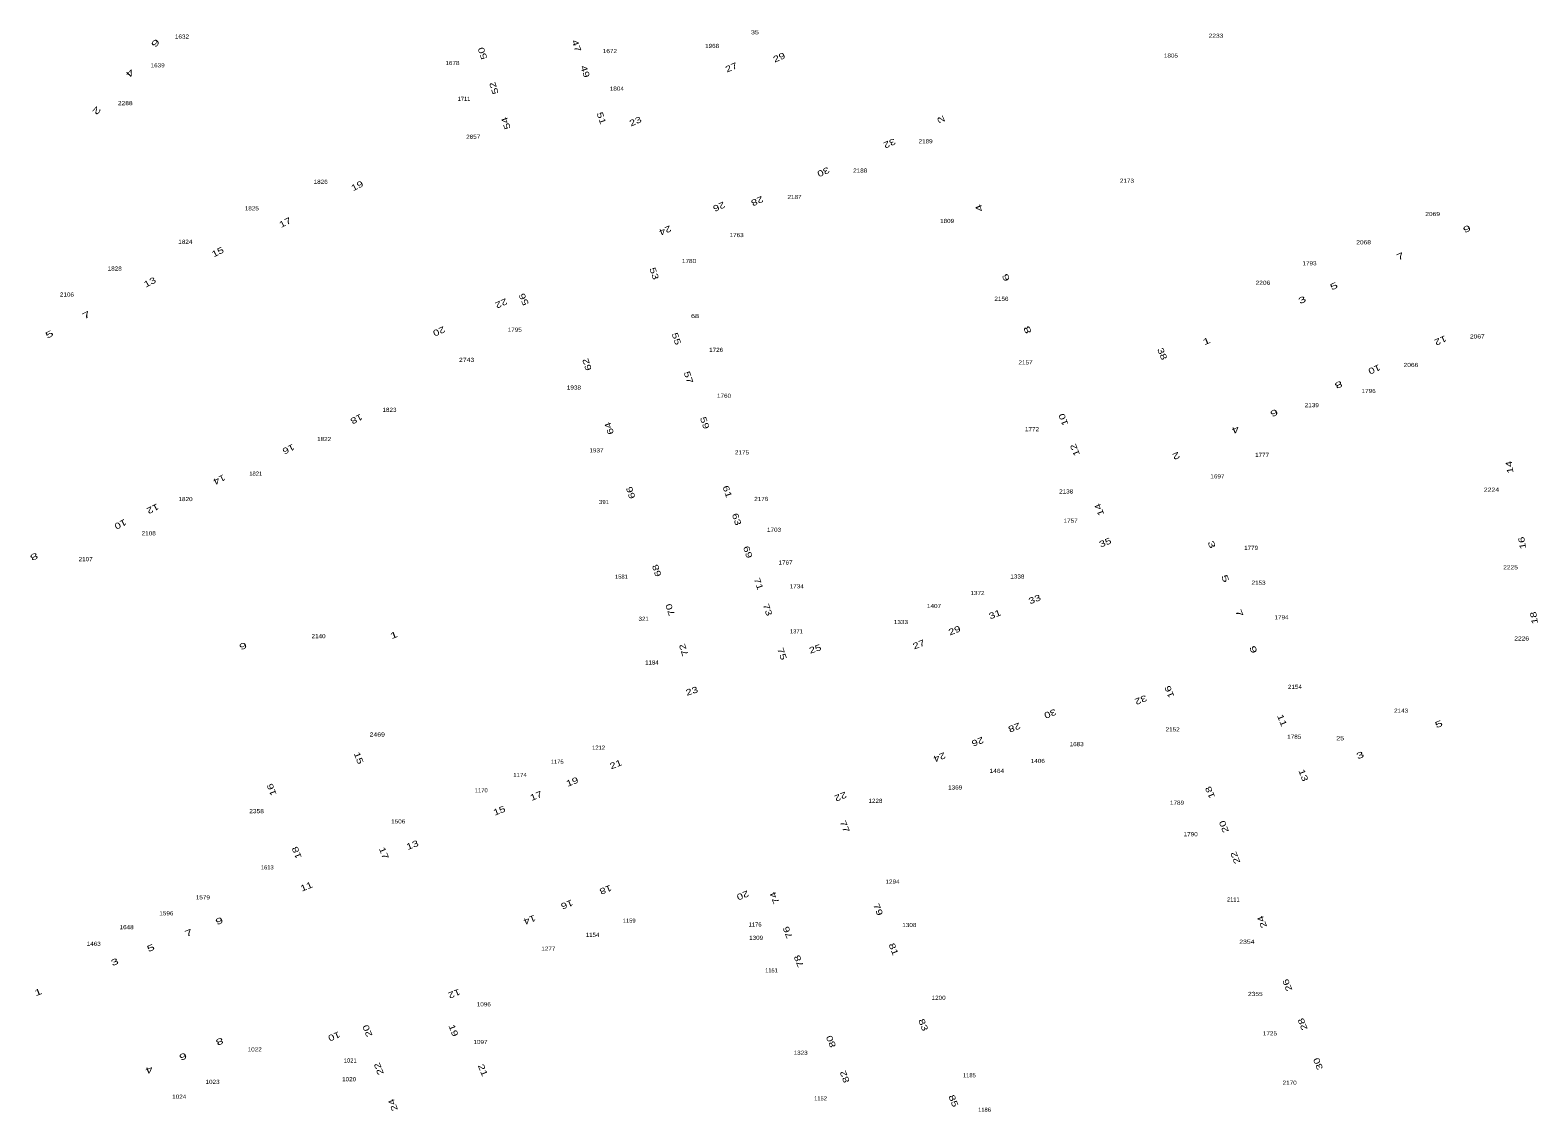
# Model space of a CAD drawing. Extents: x -828673 to -815583, y -1077737 to -1063807.
# Drawn here: x -821440 to -821074.1, y -1071841 to -1071578.4 of the extents above; entities that cross this region are included whole.
import ezdxf
from ezdxf.enums import TextEntityAlignment as Align

# ---------------------------------------------------------------- set-up
doc = ezdxf.new("R2010")
doc.units = 0
doc.header["$LTSCALE"] = 0.4
doc.layers.add('1', color=7, linetype='Continuous')
doc.layers.add('2', color=7, linetype='Continuous')

msp = doc.modelspace()

# ---------------------------------------------------------------- texts
at = {"layer": '1'}
for s, width, p in [('1632', 1.15, (-821403.179, -1071580.475)), ('35', 1.3, (-821264.142, -1071579.434)), ('2233', 1.2, (-821152.246, -1071580.27)), ('1672', 1.15, (-821299.33, -1071583.998)), ('1968', 1.15, (-821274.522, -1071582.747)), ('1639', 1.15, (-821409.077, -1071587.454)), ('1678', 1.15, (-821337.54, -1071586.895)), ('1805', 1.15, (-821163.179, -1071585.1)), ('1804', 1.15, (-821297.65, -1071593.105)), ('2288', 1.2, (-821416.942, -1071596.633)), ('2857', 1.15, (-821332.51, -1071604.802)), ('2189', 1.15, (-821222.729, -1071605.887)), ('2188', 1.15, (-821238.591, -1071613.005)), ('1826', 1.15, (-821369.518, -1071615.734)), ('2173', 1.15, (-821173.859, -1071615.469)), ('2187', 1.15, (-821254.536, -1071619.411)), ('1825', 1.15, (-821386.233, -1071622.171)), ('2069', 1.2, (-821099.682, -1071623.547)), ('1809', 1.15, (-821217.498, -1071625.231)), ('1824', 1.15, (-821402.364, -1071630.3)), ('1763', 1.15, (-821268.577, -1071628.664)), ('2068', 1.2, (-821116.425, -1071630.407)), ('1780', 1.15, (-821280.124, -1071634.961)), ('1828', 1.15, (-821419.504, -1071636.788)), ('1793', 1.15, (-821129.555, -1071635.512)), ('2206', 1.2, (-821140.877, -1071640.245)), ('2106', 1.15, (-821431.11, -1071643.099)), ('2156', 1.15, (-821204.317, -1071644.134)), ('68', 1.3, (-821278.674, -1071648.318)), ('1795', 1.15, (-821322.429, -1071651.647)), ('2067', 1.2, (-821088.837, -1071653.274)), ('1726', 1.15, (-821273.556, -1071656.53)), ('2743', 1.25, (-821334.095, -1071658.955)), ('2157', 1.15, (-821198.479, -1071659.573)), ('2066', 1.2, (-821104.944, -1071660.188)), ('1938', 1.15, (-821308.064, -1071665.676)), ('1760', 1.15, (-821271.63, -1071667.667)), ('1796', 1.15, (-821115.203, -1071666.516)), ('1823', 1.15, (-821352.833, -1071671.084)), ('2139', 1.15, (-821129.002, -1071669.948)), ('1822', 1.15, (-821368.693, -1071678.184)), ('1772', 1.15, (-821196.894, -1071675.784)), ('1937', 1.15, (-821302.597, -1071680.92)), ('2175', 1.15, (-821267.281, -1071681.424)), ('1777', 1.15, (-821141.068, -1071682.02)), ('1821', 1.05, (-821385.281, -1071686.567)), ('1697', 1.15, (-821151.912, -1071687.232)), ('1820', 1.15, (-821402.312, -1071692.75)), ('391', 1.1, (-821300.758, -1071693.452)), ('2176', 1.15, (-821262.596, -1071692.71)), ('2138', 1.15, (-821188.608, -1071690.899)), ('2224', 1.25, (-821085.404, -1071690.477)), ('2108', 1.15, (-821411.247, -1071701.048)), ('1703', 1.15, (-821259.499, -1071700.205)), ('1757', 1.15, (-821187.521, -1071697.986)), ('1779', 1.15, (-821143.731, -1071704.588)), ('2107', 1.15, (-821426.552, -1071707.335)), ('1767', 1.15, (-821256.71, -1071708.148)), ('1581', 1.05, (-821296.534, -1071711.586)), ('1338', 1.15, (-821200.453, -1071711.552)), ('2225', 1.2, (-821080.765, -1071709.322)), ('1734', 1.15, (-821253.99, -1071713.926)), ('1372', 1.15, (-821210.131, -1071715.559)), ('2153', 1.15, (-821141.924, -1071713.044)), ('1407', 1.15, (-821220.677, -1071718.699)), ('321', 1.1, (-821291.147, -1071721.809)), ('1333', 1.15, (-821228.712, -1071722.593)), ('1794', 1.15, (-821136.343, -1071721.447)), ('2140', 1.15, (-821370.03, -1071726.031)), ('1371', 1.05, (-821254.074, -1071724.854)), ('2226', 1.2, (-821078.074, -1071726.589)), ('1184', 1.1, (-821289.138, -1071732.416)), ('2154', 1.15, (-821133.1, -1071738.318)), ('2143', 1.15, (-821107.32, -1071744.115)), ('2152', 1.15, (-821162.771, -1071748.661)), ('2469', 1.25, (-821355.793, -1071749.908)), ('1683', 1.15, (-821186.061, -1071752.238)), ('1785', 1.15, (-821133.26, -1071750.444)), ('25', 1.3, (-821122.104, -1071750.816)), ('1212', 1.05, (-821302.074, -1071753.08)), ('1174', 1.1, (-821321.141, -1071759.71)), ('1175', 1.05, (-821312.121, -1071756.502)), ('1464', 1.2, (-821205.434, -1071758.728)), ('1406', 1.15, (-821195.501, -1071756.311)), ('1170', 1.05, (-821330.547, -1071763.431)), ('1369', 1.15, (-821215.544, -1071762.757)), ('1228', 1.15, (-821234.901, -1071766.003)), ('1789', 1.15, (-821161.704, -1071766.451)), ('2358', 1.2, (-821385.088, -1071768.513)), ('1506', 1.15, (-821350.705, -1071770.995)), ('1790', 1.15, (-821158.393, -1071774.105)), ('1613', 1.05, (-821382.494, -1071782.15)), ('1294', 1.15, (-821230.74, -1071785.609)), ('1579', 1.15, (-821398.111, -1071789.429)), ('1596', 1.15, (-821406.964, -1071793.304)), ('1159', 1.05, (-821294.657, -1071795.084)), ('1176', 1.05, (-821264.097, -1071796.027)), ('1308', 1.15, (-821226.674, -1071796.136)), ('1648', 1.15, (-821416.615, -1071796.665)), ('1154', 1.1, (-821303.542, -1071798.545)), ('1309', 1.15, (-821263.846, -1071799.25)), ('1463', 1.15, (-821424.603, -1071800.704)), ('1277', 1.15, (-821314.264, -1071801.879)), ('2354', 1.25, (-821144.749, -1071800.206)), ('1200', 1.15, (-821219.56, -1071813.817)), ('2355', 1.2, (-821142.691, -1071812.873)), ('1096', 1.15, (-821329.937, -1071815.398)), ('1097', 1.15, (-821330.749, -1071824.544)), ('1725', 1.15, (-821139.157, -1071822.452)), ('1022', 1.15, (-821385.527, -1071826.347)), ('1021', 1.05, (-821362.346, -1071829.039)), ('1323', 1.15, (-821253.038, -1071827.159)), ('1185', 1.05, (-821212.097, -1071832.621)), ('1023', 1.15, (-821395.752, -1071834.216)), ('1020', 1.15, (-821362.609, -1071833.575)), ('2170', 1.15, (-821134.37, -1071834.427)), ('1024', 1.15, (-821403.843, -1071837.807)), ('1152', 1.05, (-821248.218, -1071838.234)), ('1186', 1.05, (-821208.428, -1071840.991))]:
    msp.add_text(s, height=1, dxfattribs=dict(at, width=width)).set_placement(p, align=Align.CENTER)
for s, p in [('1711', (-821334.731, -1071595.606)), ('2111', (-821148.058, -1071789.951)), ('1151', (-821260.129, -1071807.157))]:
    msp.add_text(s, height=1, dxfattribs=at).set_placement(p, align=Align.CENTER)
at = {"layer": '2'}
for s, rotation, width, p in [('6', 229.001, 1.75, (-821410.1899, -1071581.075)), ('50', 108.716, 1.35, (-821329.5311, -1071583.8222)), ('47', 289.39, 1.35, (-821308.1439, -1071582.462)), ('27', 23.864, 1.35, (-821269.5729, -1071588.1427)), ('29', 23.793, 1.35, (-821257.9696, -1071585.7206)), ('4', 228.912, 1.75, (-821416.3701, -1071588.3801)), ('49', 288.306, 1.35, (-821306.0404, -1071588.6764)), ('52', 108.435, 1.35, (-821326.7669, -1071592.2522)), ('2', 228.988, 1.75, (-821424.4225, -1071597.4683)), ('54', 108.779, 1.35, (-821323.8645, -1071600.7869)), ('51', 288.402, 1.35, (-821302.093, -1071600.0187)), ('23', 23.862, 1.35, (-821292.8574, -1071601.237)), ('2', 113.6, 1.65, (-821218.3063, -1071599.8228)), ('32', 203.639, 1.35, (-821231.7593, -1071605.2158)), ('30', 203.768, 1.35, (-821247.8297, -1071612.1668)), ('19', 27.044, 1.35, (-821360.3275, -1071616.8746)), ('28', 203.763, 1.35, (-821263.8778, -1071619.2327)), ('26', 203.789, 1.35, (-821273.1455, -1071620.5883)), ('4', 111.683, 1.65, (-821209.0423, -1071621.3411)), ('17', 27.055, 1.35, (-821377.8006, -1071625.7723)), ('24', 203.123, 1.35, (-821286.2015, -1071626.3637)), ('9', 23.143, 1.65, (-821091.0823, -1071627.3578)), ('15', 27.027, 1.35, (-821394.1653, -1071632.943)), ('7', 23.083, 1.65, (-821107.2406, -1071634.0066)), ('53', 288.592, 1.35, (-821289.284, -1071637.7359)), ('6', 111.68, 1.65, (-821202.5332, -1071638.2011)), ('13', 27.099, 1.35, (-821410.6301, -1071640.2632)), ('5', 23.683, 1.65, (-821123.3478, -1071641.2342)), ('22', 204.084, 1.35, (-821325.9819, -1071644.0647)), ('56', 113.931, 1.35, (-821319.5521, -1071643.4742)), ('3', 23.715, 1.65, (-821131.0546, -1071644.5846)), ('7', 27.118, 1.7, (-821426.0364, -1071648.256)), ('5', 27.566, 1.7, (-821435.0196, -1071652.9078)), ('20', 203.602, 1.35, (-821341.0902, -1071650.8497)), ('55', 288.706, 1.35, (-821283.8852, -1071653.563)), ('8', 111.783, 1.65, (-821197.3047, -1071650.9088)), ('12', 203.741, 1.35, (-821098.0495, -1071653.0664)), ('38', 292.612, 1.35, (-821165.9819, -1071657.2711)), ('1', 22.413, 1.65, (-821154.2875, -1071654.5932)), ('62', 108.653, 1.35, (-821304.1824, -1071659.3669)), ('10', 203.719, 1.35, (-821114.1023, -1071660.0857)), ('57', 288.397, 1.35, (-821280.9581, -1071662.9448)), ('8', 203.86, 1.65, (-821122.7916, -1071663.8267)), ('6', 203.732, 1.65, (-821138.4507, -1071670.6614)), ('18', 206.968, 1.35, (-821361.1414, -1071672.1436)), ('64', 108.69, 1.35, (-821298.8005, -1071674.8648)), ('59', 288.751, 1.35, (-821277.0221, -1071673.9984)), ('10', 111.239, 1.35, (-821188.5916, -1071672.6897)), ('4', 203.378, 1.65, (-821147.8069, -1071674.753)), ('16', 206.96, 1.35, (-821377.6435, -1071679.4574)), ('12', 111.587, 1.35, (-821185.7903, -1071680.0584)), ('2', 203.184, 1.65, (-821162.2117, -1071681.0809)), ('14', 99.106, 1.35, (-821080.29, -1071684.3967)), ('14', 206.847, 1.35, (-821394.4443, -1071686.8555)), ('66', 108.15, 1.35, (-821293.5826, -1071690.4776)), ('61', 288.644, 1.35, (-821271.5388, -1071690.6692)), ('12', 206.468, 1.35, (-821410.5797, -1071693.9335)), ('63', 288.666, 1.35, (-821269.2813, -1071697.385)), ('14', 111.272, 1.35, (-821179.8886, -1071694.5556)), ('10', 207.22, 1.35, (-821418.4439, -1071697.7049)), ('69', 288.435, 1.35, (-821266.5631, -1071705.3418)), ('35', 21.296, 1.35, (-821178.8659, -1071703.4839)), ('3', 291.634, 1.65, (-821153.9795, -1071703.549)), ('16', 99.474, 1.35, (-821077.2306, -1071702.7764)), ('8', 206.469, 1.7, (-821439.3997, -1071705.5701)), ('68', 108.435, 1.35, (-821287.2639, -1071709.3812)), ('5', 291.682, 1.65, (-821150.6887, -1071711.8099)), ('71', 288.653, 1.35, (-821263.9456, -1071713.0471)), ('70', 109.125, 1.35, (-821284.0124, -1071718.8942)), ('73', 288.459, 1.35, (-821261.7685, -1071719.3385)), ('33', 21.448, 1.35, (-821195.9832, -1071717.2601)), ('31', 21.565, 1.35, (-821205.6352, -1071720.9222)), ('7', 291.66, 1.65, (-821147.2862, -1071720.2127)), ('18', 99.098, 1.35, (-821074.3508, -1071720.9716)), ('1', 21.584, 1.65, (-821351.4914, -1071725.9552)), ('29', 21.644, 1.35, (-821215.4336, -1071724.8341)), ('6', 201.956, 1.65, (-821388.6416, -1071727.2396)), ('72', 108.422, 1.35, (-821280.7175, -1071728.6465)), ('75', 288.905, 1.35, (-821258.2511, -1071730.0575)), ('25', 18.683, 1.35, (-821249.2903, -1071729.3299)), ('27', 21.415, 1.35, (-821224.0953, -1071728.2267)), ('9', 291.388, 1.65, (-821143.8863, -1071729.0415)), ('23', 18.53, 1.35, (-821279.2139, -1071739.5566)), ('32', 201.546, 1.35, (-821170.7506, -1071740.3136)), ('16', 111.549, 1.35, (-821162.8784, -1071738.763)), ('30', 201.545, 1.35, (-821192.7436, -1071743.6666)), ('28', 201.383, 1.35, (-821201.4446, -1071747.0143)), ('11', 291.99, 1.35, (-821136.8966, -1071746.2312)), ('5', 21.542, 1.65, (-821097.9204, -1071747.5679)), ('26', 201.107, 1.35, (-821210.3489, -1071750.4595)), ('15', 291.3, 1.35, (-821360.9848, -1071755.3681)), ('24', 201.934, 1.35, (-821219.6088, -1071754.2241)), ('3', 21.75, 1.65, (-821117.0034, -1071755.1167)), ('21', 21.304, 1.35, (-821297.6425, -1071757.3335)), ('13', 291.329, 1.35, (-821131.7369, -1071759.5572)), ('16', 111.03, 1.35, (-821380.7255, -1071762.5206)), ('19', 21.678, 1.35, (-821308.203, -1071761.5653)), ('18', 112.419, 1.35, (-821153.0043, -1071763.18)), ('17', 21.578, 1.35, (-821316.9663, -1071764.9869)), ('22', 201.725, 1.35, (-821243.6189, -1071763.78)), ('15', 21.517, 1.35, (-821325.9016, -1071768.5803)), ('77', 291.493, 1.35, (-821243.0299, -1071771.9947)), ('20', 111.007, 1.35, (-821149.6349, -1071771.5154)), ('18', 111.667, 1.35, (-821374.6474, -1071777.8189)), ('17', 291.749, 1.35, (-821354.8675, -1071778.4646)), ('13', 21.149, 1.35, (-821347.0006, -1071776.9186)), ('22', 111.801, 1.35, (-821146.8648, -1071779.035)), ('11', 22.214, 1.35, (-821372.6955, -1071787.0039)), ('18', 201.566, 1.35, (-821300.6228, -1071786.3908)), ('20', 201.69, 1.35, (-821267.3488, -1071787.764)), ('74', 111.549, 1.35, (-821258.6895, -1071788.808)), ('16', 201.664, 1.35, (-821310.0211, -1071789.9823)), ('79', 291.636, 1.35, (-821234.9313, -1071792.1365)), ('9', 21.379, 1.65, (-821393.8644, -1071795.3544)), ('14', 201.689, 1.35, (-821319.0768, -1071793.6999)), ('24', 111.827, 1.35, (-821140.3806, -1071794.6169)), ('7', 21.856, 1.65, (-821401.2697, -1071798.2469)), ('76', 111.445, 1.35, (-821255.4908, -1071797.1932)), ('5', 21.779, 1.65, (-821410.4828, -1071801.9013)), ('81', 291.594, 1.35, (-821231.1743, -1071801.783)), ('3', 21.257, 1.65, (-821419.2494, -1071805.3106)), ('78', 111.951, 1.35, (-821252.8027, -1071804.1599)), ('26', 111.801, 1.35, (-821134.2508, -1071809.97)), ('1', 21.217, 1.65, (-821437.8269, -1071812.6301)), ('12', 201.584, 1.35, (-821337.3556, -1071811.6193)), ('20', 111.948, 1.35, (-821357.4836, -1071821.0738)), ('19', 291.435, 1.35, (-821337.9852, -1071821.4954)), ('83', 291.397, 1.35, (-821223.9763, -1071820.1664)), ('28', 111.404, 1.35, (-821130.5358, -1071819.4607)), ('8', 201.668, 1.65, (-821394.3041, -1071823.2401)), ('10', 202.598, 1.35, (-821366.5263, -1071821.9967)), ('80', 112.237, 1.35, (-821244.9868, -1071823.6483)), ('6', 202.328, 1.65, (-821403.2026, -1071826.8893)), ('30', 111.59, 1.35, (-821126.7866, -1071829.085)), ('4', 201.189, 1.65, (-821411.3794, -1071830.1416)), ('22', 111.288, 1.35, (-821354.7219, -1071830.2898)), ('21', 291.801, 1.35, (-821330.8482, -1071831.152)), ('82', 111.475, 1.35, (-821241.6577, -1071832.2021)), ('24', 111.351, 1.35, (-821351.2864, -1071839.0696)), ('85', 291.335, 1.35, (-821216.648, -1071838.6116))]:
    msp.add_text(s, height=1.5, rotation=rotation, dxfattribs=dict(at, width=width)).set_placement(p, align=Align.CENTER)

doc.saveas('drawing.dxf')
